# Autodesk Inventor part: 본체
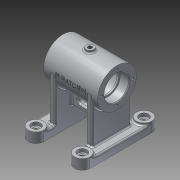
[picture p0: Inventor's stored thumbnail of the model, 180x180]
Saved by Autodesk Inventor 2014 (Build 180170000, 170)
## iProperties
Created: 2015-11
Part Number: 본체
Material: 알루미늄 6061
Document SubType Name: Modeling
Designer: 702
Density: 2.71 g/cm^3
Appearance: 알루미늄 - 평지
Mass: 359.022 g
Surface Area: 459.453 cm^2
Volume: 132.48 cm^3
Author: 702
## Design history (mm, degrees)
sketch "스케치1"
  geometry: C1 r 25 at (0, 0); C2 r 21 at (0, 0); 1 further point
  constraints: 2 centre point, 2 coincident
  dimensions: "d0" = 50 diameter of C1; "d1" = 42 diameter of C2
extrude "돌출1" new body sketch "스케치1" stored distance "d2" = 70; taper "d3" = 0 deg
extrude "돌출2" cut sketch "스케치1" stored distance "d4" = 42; taper "d5" = 0 deg
sketch "스케치2"
  geometry: C1 r 25 at (0, 0) reference; C2 r 16 at (0, 0); C3 r 14 at (0, 0)
  constraints: 2 centre point, 2 coincident
  dimensions: "d6" = 32 diameter of C2; "d7" = 28 diameter of C3
extrude "돌출3" cut sketch "스케치2" stored distance "d8" = 42; taper "d9" = 0 deg
extrude "돌출4" cut sketch "스케치2" distance "d10" = 12; taper "d11" = 0 deg
node "작업 평면1"
sketch "스케치3"
  geometry: L1 (-25, 0)-(-25, -68); L2 (25, 0)-(25, -68); L3 (-25, -68)-(25, -68); A1 r 25 centre (0, 0) between (-25, 0) and (25, 0) reference; 1 further point
  constraints: 6 end point, 2 point on circle, 2 tangent, 1 parallel, 1 perpendicular, 1 vertical
  dimensions: "d13" = 68 distance from line of L3 point (0, 0)
extrude "돌출5" join sketch "스케치3" distance "d14" = 8; taper "d15" = 0 deg
sketch "스케치4"
  geometry: L1 (0, 0)-(0, 50) reference; L2 (0, 50)-(-8, 50) reference; L3 (-8, 0)-(-8, 50) reference; L4 (0, 0)-(-8, 0) reference; L5 (-20, 65)-(-20, -15); L6 (0, -15)-(0, 65); A1 r 10 centre (-10, -15) between (-20, -15) and (0, -15); A2 r 10 centre (-10, 65) between (0, 65) and (-20, 65); 3 further points
  constraints: 4 end point, 4 point on circle, 4 tangent, 3 midpoint, 2 centre point, 1 horizontal alignment, 1 parallel, 1 perpendicular
  dimensions: "d16" = 20 distance between parallel lines of L6 L5; "d17" = 80 distance of A1.centre A2.centre
extrude "돌출6" join sketch "스케치4" distance "d18" = 10; taper "d19" = 0 deg
sketch "스케치5"
  geometry: C1 r 10 at (10, 65); C2 r 10 at (10, -15); A1 r 10 centre (10, -15) between (0, -15) and (20, -15) reference; A2 r 10 centre (10, 65) between (20, 65) and (0, 65) reference; 1 further point
  constraints: 2 centre point, 2 coincident, 1 equal radius
  dimensions: "d20" = 20 diameter of C1
extrude "돌출7" join sketch "스케치5" distance "d21" = 3; taper "d22" = 0 deg
sketch "스케치6"
  geometry: C1 r 10 at (0, 0) reference; C2 r 6 at (0, 0); C3 r 3 at (0, 0); C4 r 10 at (0, 80) reference; C5 r 6 at (0, 80); C6 r 3 at (0, 80); 1 further point
  constraints: 4 centre point, 4 coincident, 2 equal radius
  dimensions: "d23" = 12 diameter of C2; "d24" = 6 diameter of C3
extrude "돌출8" cut sketch "스케치6" distance "d25" = 4; taper "d26" = 0 deg
extrude "돌출9" cut sketch "스케치6" stored distance "d27" = 4; taper "d28" = 0 deg
sketch "스케치7"
  geometry: C1 r 16 at (0, 0) reference; 1 further point
  constraints: 1 vertical alignment
  dimensions: "d32" = 20 distance of C1.centre point (0, 20)
hole "구멍1" sketch "스케치7" at (0, 20) diameter "d33" = 3.242; stored, may be unused: countersink angle "d37" = 90 deg, drill point angle "d39" = 118 deg; dims "d34" = 8, "d35" = 4, "d36" = 2, "d38" = 10
sketch "스케치8"
  geometry: L1 (0, 0)-(25, 0); L2 (0, 0)-(14, -24.249); 1 further point
  constraints: 4 end point, 1 horizontal, 1 horizontal alignment, 1 other
  dimensions: "d43" = 60 deg angle of L1 L2; "d44" = 28 distance of L1.start L2.end
node "작업 평면2"
sketch "스케치9"
  geometry: C1 r 6 at (0, 0); 1 further point
  constraints: 1 centre point, 1 coincident
  dimensions: "d45" = 12 diameter of C1
extrude "돌출10" join sketch "스케치9" stored distance "d46" = 4; taper "d47" = 0 deg
hole "구멍2" diameter "d50" = 5.188; stored, may be unused: countersink angle "d54" = 90 deg, drill point angle "d56" = 118 deg; dims "d48" = 10, "d49" = 10, "d51" = 8, "d52" = 4, "d53" = 2, "d55" = 10
node "작업 평면3"
sketch "스케치10"
  geometry: C1 r 5 at (0, 0); 1 further point
  constraints: 1 centre point, 1 coincident
  dimensions: "d58" = 10 diameter of C1
extrude "돌출11" join sketch "스케치10" stored distance "d59" = 4; taper "d60" = 0 deg
hole "구멍3" diameter "d63" = 5.188; stored, may be unused: countersink angle "d67" = 90 deg, drill point angle "d69" = 118 deg; dims "d61" = 10, "d62" = 10, "d64" = 8, "d65" = 4, "d66" = 2, "d68" = 10
sketch "스케치11"
  geometry: L1 (-20, -45)-(20, -45); L2 (-20, 0)-(-20, -58) reference; L3 (20, 0)-(20, -58) reference; L4 (35, -25)-(-35, -25) reference; L5 (21, -21)-(-21, -21) reference; L6 (-20, -45)-(-20, -21); L7 (-20, -21)-(20, -21); L8 (20, -21)-(20, -45); L9 (-8, -31.5)-(8, -31.5); L10 (8, -38.5)-(-8, -38.5); L11 (33, -68)-(27, -68) reference; A1 r 3.5 centre (8, -35) between (8, -38.5) and (8, -31.5); A2 r 3.5 centre (-8, -35) between (-8, -31.5) and (-8, -38.5); 3 further points
  constraints: 12 end point, 6 point on line, 4 point on circle, 4 tangent, 2 centre point, 2 midpoint, 2 vertical alignment, 1 collinear, 1 horizontal, 1 parallel, 1 perpendicular
  dimensions: "d70" = 20 distance between parallel lines of L4 L1; "d71" = 3.5 radius of A1; "d72" = 23 dimension on A1 A2; "d73" = 33 distance from line of L11 A1.centre
extrude "돌출12" join sketch "스케치11" stored distance "d74" = 8; taper "d75" = 0 deg
node "작업 평면4"
sketch "스케치12"
  geometry: 2 further points
  constraints: 2 coincident, 1 other
feature "엠보싱1" sketch "스케치12" dims "d13" = 68, "d76" = 0.5, "d77" = 0
fillet "모깎기1" dims "d78" = 3, "d79" = 2
chamfer "모따기2" distance "d80" = 1; stored, may be unused: second distance "d81" = 2, angle "d82" = 45 deg
fillet "모깎기2" dims "d83" = 0.3, "d84" = 2
node "솔리드1"
pattern_circular "원형 패턴1" dims angle "d41" = 360 deg
mirror "대칭1"
other parameters: "d57" = 28
